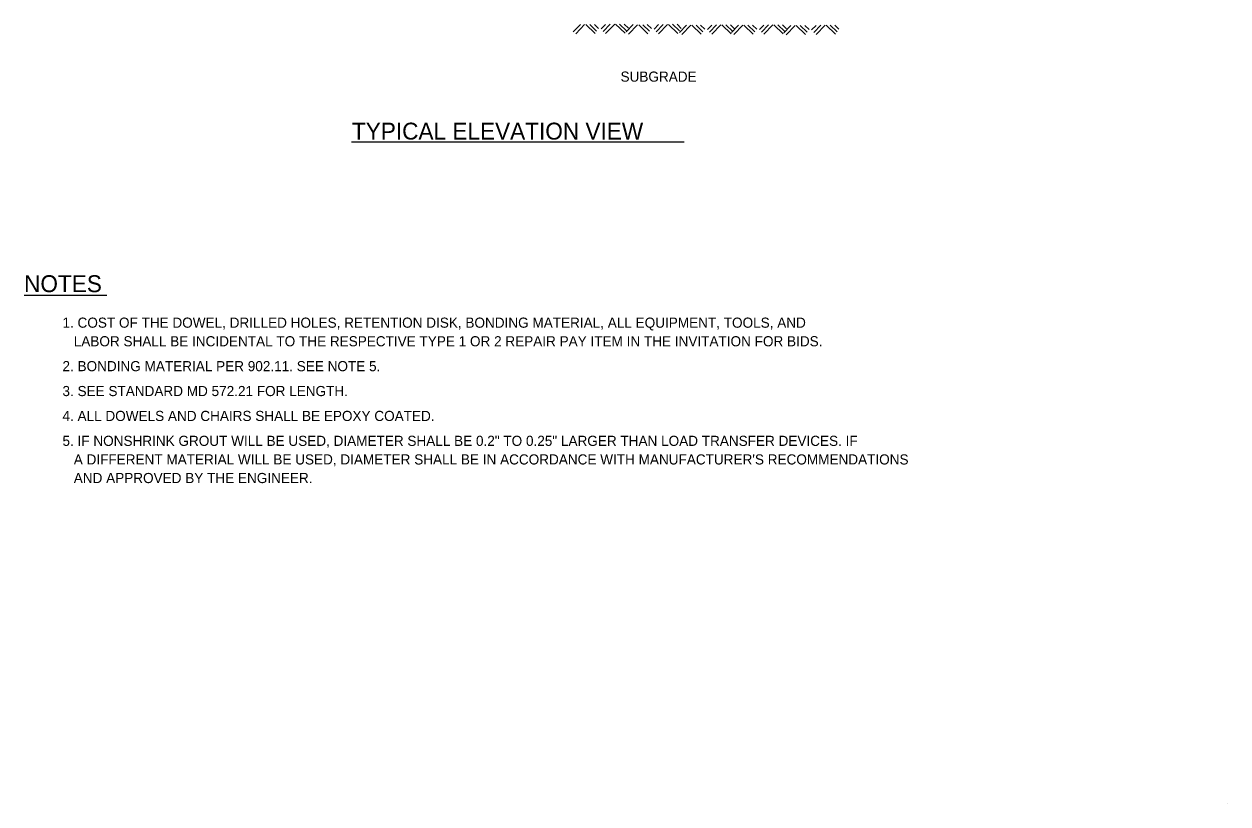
# Model space of a CAD drawing. Extents: x 2.92 to 10.05, y 1.3 to 10.63.
# Drawn here: x 2.92 to 10.05, y 1.3 to 5.92 of the extents above; entities that cross this region are included whole.
import ezdxf

# ---------------------------------------------------------------- set-up
doc = ezdxf.new("R2010")
doc.units = 0
for name, color, linetype in [('DETL-NOTE', 7, 'Continuous'), ('DETL-PATT', 7, 'Continuous'), ('DETL-TITL', 7, 'Continuous'), ('TTLB-TEXT', 7, 'Continuous')]:
    doc.layers.add(name, color=color, linetype=linetype)

msp = doc.modelspace()

# ---------------------------------------------------------------- linework, layer by layer
at = {"layer": 'DETL-NOTE'}
msp.add_line((2.9235, 4.3144), (3.4126, 4.3144), dxfattribs=at)
at = {"layer": 'DETL-PATT'}
for p, q in [((6.2166, 5.9154), (6.1746, 5.872)), ((6.3125, 5.8761), (6.2725, 5.9147)), ((6.2999, 5.9151), (6.324, 5.8918)), ((6.3397, 5.8885), (6.3661, 5.9159)), ((6.3935, 5.9164), (6.352, 5.8735)), ((6.3661, 5.8611), (6.42, 5.9167)), ((6.4251, 5.9168), (6.4809, 5.8629)), ((6.4897, 5.8776), (6.4487, 5.9171)), ((6.476, 5.9175), (6.5013, 5.8933)), ((6.6524, 5.8875), (6.6788, 5.9149)), ((6.7062, 5.9154), (6.6647, 5.8725)), ((6.6788, 5.8601), (6.7327, 5.9158)), ((6.7378, 5.9158), (6.7936, 5.8619)), ((6.8024, 5.8766), (6.7615, 5.9161)), ((6.7887, 5.9165), (6.814, 5.8923)), ((6.189, 5.8596), (6.2416, 5.9143)), ((6.2487, 5.9144), (6.3036, 5.8614)), ((6.5293, 5.9144), (6.4873, 5.8711)), ((6.5017, 5.8586), (6.5544, 5.9133)), ((6.5615, 5.9134), (6.6163, 5.8604)), ((6.6252, 5.8751), (6.5852, 5.9137)), ((6.6126, 5.9141), (6.6367, 5.8908)), ((6.845, 5.9115), (6.803, 5.8681)), ((6.8174, 5.8556), (6.87, 5.9104)), ((6.8771, 5.9105), (6.932, 5.8575)), ((6.9409, 5.8722), (6.9009, 5.9108)), ((6.9283, 5.9112), (6.9524, 5.8879)), ((6.9681, 5.8846), (6.9945, 5.912)), ((7.0218, 5.9124), (6.9804, 5.8696)), ((6.9945, 5.8571), (7.0484, 5.9128)), ((7.0535, 5.9129), (7.1093, 5.8589)), ((7.1181, 5.8736), (7.0771, 5.9131)), ((7.1044, 5.9136), (7.1296, 5.8893)), ((7.1527, 5.9115), (7.1107, 5.8681)), ((7.1251, 5.8556), (7.1777, 5.9104)), ((7.1848, 5.9105), (7.2397, 5.8575)), ((7.2485, 5.8722), (7.2085, 5.9108)), ((7.236, 5.9112), (7.2601, 5.8879)), ((7.2758, 5.8846), (7.3022, 5.912)), ((7.3295, 5.9124), (7.2881, 5.8696)), ((7.3022, 5.8571), (7.356, 5.9128)), ((7.3611, 5.9129), (7.4169, 5.8589)), ((7.4258, 5.8736), (7.3848, 5.9131)), ((7.4121, 5.9136), (7.4373, 5.8893)), ((7.4625, 5.9095), (7.4205, 5.8662)), ((7.4348, 5.8537), (7.4875, 5.9084)), ((7.4946, 5.9085), (7.5495, 5.8555)), ((7.5583, 5.8702), (7.5183, 5.9088)), ((7.5457, 5.9092), (7.5698, 5.8859)), ((7.5855, 5.8826), (7.612, 5.91)), ((7.6393, 5.9105), (7.5979, 5.8676)), ((7.612, 5.8552), (7.6658, 5.9109)), ((7.6709, 5.9109), (7.7267, 5.857)), ((7.7356, 5.8717), (7.6946, 5.9112)), ((7.7219, 5.9116), (7.7471, 5.8874))]:
    msp.add_line(p, q, dxfattribs=at)
at = {"layer": 'DETL-TITL'}
msp.add_line((4.8607, 5.2216), (6.8308, 5.2216), dxfattribs=at)
at = {"layer": 'TTLB-TEXT'}
msp.add_line((10.0495, 1.3034), (10.0495, 1.3034), dxfattribs=at)

# ---------------------------------------------------------------- texts
at = {"layer": 'DETL-NOTE'}
for s, height, p in [('SUBGRADE', 0.06, (6.4542, 5.5767)), ('NOTES', 0.1, (2.9235, 4.3315)), ('1. COST OF THE DOWEL, DRILLED HOLES, RETENTION DISK, BONDING MATERIAL, ALL EQUIPMENT, TOOLS, AND ', 0.06, (3.1508, 4.1209)), ('   LABOR SHALL BE INCIDENTAL TO THE RESPECTIVE TYPE 1 OR 2 REPAIR PAY ITEM IN THE INVITATION FOR BIDS.', 0.06, (3.1508, 4.0109)), ('2. BONDING MATERIAL PER 902.11. SEE NOTE 5.', 0.06, (3.1508, 3.8636)), ('3. SEE STANDARD MD 572.21 FOR LENGTH.', 0.06, (3.1508, 3.7163)), ('4. ALL DOWELS AND CHAIRS SHALL BE EPOXY COATED.', 0.06, (3.1508, 3.569)), ('5. IF NONSHRINK GROUT WILL BE USED, DIAMETER SHALL BE 0.2" TO 0.25" LARGER THAN LOAD TRANSFER DEVICES. IF ', 0.06, (3.1508, 3.4217)), ("   A DIFFERENT MATERIAL WILL BE USED, DIAMETER SHALL BE IN ACCORDANCE WITH MANUFACTURER'S RECOMMENDATIONS ", 0.06, (3.1508, 3.3117)), ('   AND APPROVED BY THE ENGINEER.', 0.06, (3.1508, 3.2017))]:
    msp.add_text(s, height=height, dxfattribs=at).set_placement(p)
at = {"layer": 'DETL-TITL'}
msp.add_text('TYPICAL ELEVATION VIEW', height=0.1, dxfattribs=at).set_placement((4.8642, 5.2342))

doc.saveas('drawing.dxf')
